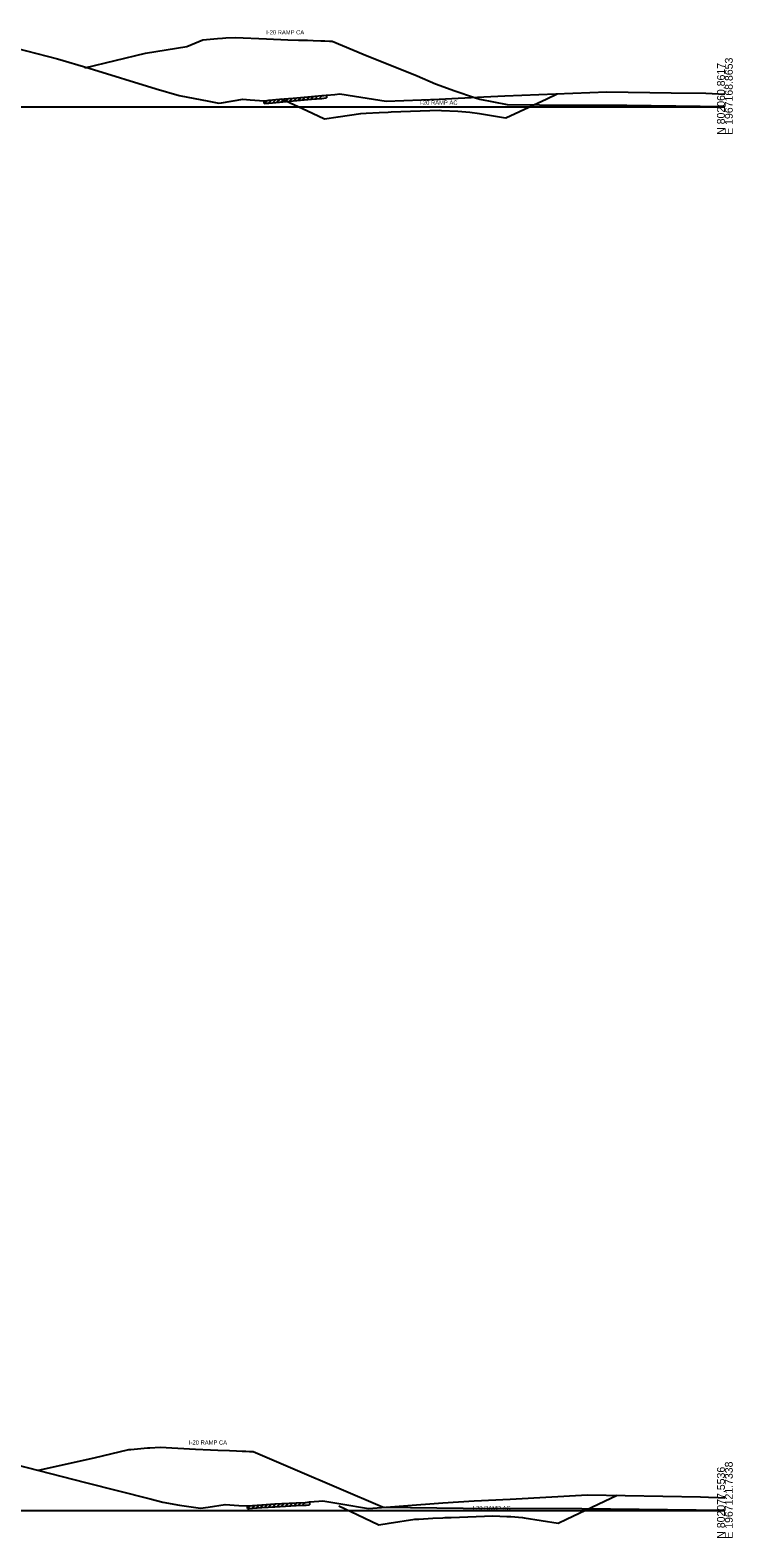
# Model space of a CAD drawing. Extents: x -26 to 1986619, y -10 to 827846.
# Drawn here: x 352 to 603, y 23990 to 24527 of the extents above; entities that cross this region are included whole.
import ezdxf

# ---------------------------------------------------------------- set-up
doc = ezdxf.new("R2010")
doc.units = 0
for name, color, linetype in [('RD_GPK_XS_Cell', 7, 'Continuous'), ('RD_TX_Misc1', 7, 'Continuous'), ('RD_XS_ExGround', 7, 'Continuous'), ('RD_XS_ExPaveRet', 7, 'Continuous'), ('RD_XS_Pave', 7, 'Continuous')]:
    doc.layers.add(name, color=color, linetype=linetype)

msp = doc.modelspace()

# ---------------------------------------------------------------- linework, layer by layer
at = {"layer": 'RD_GPK_XS_Cell'}
for p, q in [((300, 24500), (600, 24500)), ((300, 24000), (600, 24000))]:
    msp.add_line(p, q, dxfattribs=at)
at = {"layer": 'RD_XS_ExGround'}
for points in [[(339.96, 24522.77), (362.21, 24517.09), (373.39, 24513.69), (397.31, 24506.44), (405.57, 24503.96), (416.08, 24501.93), (419.7, 24501.28), (420.65, 24501.43), (428.19, 24502.65), (430.8, 24502.49), (435.86, 24502.14), (436.84, 24502.24), (437.49, 24502.31), (441.22, 24502.67), (446.1, 24503.09), (452.68, 24503.65), (456.35, 24503.95), (457.09, 24504.02), (457.99, 24504.14), (460.96, 24504.4), (462.77, 24504.56), (467.97, 24503.75), (479.27, 24502), (498.23, 24502.73), (514.05, 24503.49), (521.59, 24503.88), (557.93, 24505.29), (580.81, 24504.92), (593.18, 24504.88), (600, 24504.52)], [(343.06, 24017.49), (372.15, 24009.99), (395.23, 24004.26), (399.68, 24002.96), (405.69, 24001.96), (413.09, 24000.82), (415.84, 24001.22), (421.97, 24002.13), (426.76, 24001.88), (429.91, 24001.72), (430.44, 24001.76), (431.64, 24001.82), (434.95, 24002.06), (439.56, 24002.38), (447.22, 24002.77), (450.39, 24002.92), (450.73, 24002.94), (452.02, 24003.1), (455.29, 24003.36), (456.67, 24003.46), (463.18, 24002.37), (472.94, 24000.77), (499.5, 24002.77), (510.62, 24003.49), (523.46, 24004.14), (551.06, 24005.67), (591.36, 24004.9), (594.15, 24004.84), (597.57, 24004.69), (600, 24004.57)]]:
    msp.add_lwpolyline(points, dxfattribs=at)
at = {"layer": 'RD_XS_ExPaveRet'}
for p, q in [((435.86, 24501.14), (436.98, 24502.26)), ((435.86, 24501.14), (435.86, 24502.14)), ((437.36, 24501.3), (438.47, 24502.4)), ((438.86, 24501.44), (439.97, 24502.55)), ((440.36, 24501.58), (441.46, 24502.69)), ((441.86, 24501.72), (442.95, 24502.82)), ((443.36, 24501.85), (444.45, 24502.95)), ((444.86, 24501.98), (445.95, 24503.08)), ((446.1, 24502.09), (452.68, 24502.65)), ((446.36, 24502.11), (447.45, 24503.2)), ((447.86, 24502.24), (448.95, 24503.33)), ((449.36, 24502.37), (450.45, 24503.46)), ((450.86, 24502.49), (451.95, 24503.59)), ((452.36, 24502.62), (453.45, 24503.71)), ((452.68, 24502.65), (456.35, 24502.95)), ((453.86, 24502.74), (454.95, 24503.83)), ((455.36, 24502.87), (456.45, 24503.96)), ((456.35, 24502.95), (457.09, 24503.02)), ((457.09, 24503.02), (457.99, 24503.14)), ((457.99, 24504.14), (457.99, 24503.14)), ((435.86, 24501.14), (436.84, 24501.24)), ((436.84, 24501.24), (437.49, 24501.31)), ((437.49, 24501.31), (441.22, 24501.67)), ((441.22, 24501.67), (446.1, 24502.09)), ((446.41, 24001.73), (447.46, 24002.78)), ((447.91, 24001.8), (448.96, 24002.85)), ((449.41, 24001.87), (450.46, 24002.92)), ((452.02, 24003.1), (452.02, 24002.1)), ((429.91, 24000.72), (430.97, 24001.79)), ((429.91, 24000.72), (429.91, 24001.72)), ((429.91, 24000.72), (430.44, 24000.76)), ((430.44, 24000.76), (431.64, 24000.82)), ((431.41, 24000.81), (432.48, 24001.88)), ((431.64, 24000.82), (434.95, 24001.06)), ((432.91, 24000.91), (433.98, 24001.99)), ((434.41, 24001.02), (435.48, 24002.09)), ((434.95, 24001.06), (439.56, 24001.38)), ((435.91, 24001.12), (436.98, 24002.2)), ((437.41, 24001.23), (438.48, 24002.3)), ((438.91, 24001.33), (439.97, 24002.4)), ((439.56, 24001.38), (447.22, 24001.77)), ((440.41, 24001.42), (441.46, 24002.47)), ((441.91, 24001.5), (442.96, 24002.55)), ((443.41, 24001.57), (444.46, 24002.63)), ((444.91, 24001.65), (445.96, 24002.7)), ((447.22, 24001.77), (450.39, 24001.92)), ((450.39, 24001.92), (450.73, 24001.94)), ((450.73, 24001.94), (452.02, 24002.1))]:
    msp.add_line(p, q, dxfattribs=at)
at = {"layer": 'RD_XS_Pave'}
for points in [[(371.85, 24513.9), (393.56, 24519.1), (408.25, 24521.49), (413.91, 24523.84), (419.23, 24524.3), (420.92, 24524.45), (422.19, 24524.52), (425.59, 24524.71), (436.61, 24524.16), (444.28, 24523.8), (448.03, 24523.76), (451.29, 24523.71), (453.22, 24523.62), (455.96, 24523.49), (456.5, 24523.46), (456.82, 24523.45), (457.39, 24523.42), (459.12, 24523.34), (460.05, 24523.3), (471.13, 24518.77), (490.37, 24510.99), (496.82, 24508.16), (503.78, 24505.71), (510.71, 24503.28), (512.72, 24502.71), (522.36, 24500.85), (545.44, 24500.54), (549.38, 24500.57), (565.1, 24500.56), (600, 24500.13)], [(441.99, 24502.85), (450.97, 24498.64), (457.32, 24495.65), (462.13, 24496.37), (470.27, 24497.57), (472.19, 24497.7), (476.74, 24498.01), (480.03, 24498.11), (481.06, 24498.15), (484.57, 24498.27), (498.32, 24498.74), (498.96, 24498.72), (504.8, 24498.46), (509.11, 24498.12), (512.51, 24497.57), (521.16, 24496.19), (521.97, 24496.06), (536.49, 24502.8), (540.26, 24504.55)], [(355.36, 24014.36), (375.23, 24018.83), (387.54, 24021.76), (388.26, 24021.83), (394.27, 24022.35), (395.01, 24022.39), (398.76, 24022.58), (411.35, 24021.88), (416.72, 24021.6), (419.26, 24021.55), (423.46, 24021.47), (426, 24021.33), (427.95, 24021.23), (428.4, 24021.2), (428.77, 24021.18), (429.32, 24021.15), (430.54, 24021.09), (431.88, 24021.02), (446.81, 24014.6), (477.94, 24001.35), (478.56, 24001.28), (516.14, 24000.77), (522.73, 24000.82), (549.01, 24000.8), (600, 24000.18)], [(462.46, 24001.68), (468.92, 23998.63), (476.69, 23994.96), (480.4, 23995.53), (489.51, 23996.91), (490.9, 23997.01), (495.93, 23997.37), (499.53, 23997.49), (500.2, 23997.52), (502.5, 23997.6), (517.3, 23998.16), (522.24, 23997.96), (523.69, 23997.9), (527.93, 23997.57), (528.46, 23997.49), (540.64, 23995.56), (543.61, 23996.96), (561.65, 24005.45)]]:
    msp.add_lwpolyline(points, dxfattribs=at)

# ---------------------------------------------------------------- texts
at = {"layer": 'RD_GPK_XS_Cell'}
for s, p in [('N 802060.8617', (600, 24490)), ('E 1967168.8653', (602.8, 24490)), ('N 802077.5536', (600, 23990)), ('E 1967121.7338', (602.8, 23990))]:
    msp.add_text(s, height=2.8, rotation=90, dxfattribs=at).set_placement(p)
at = {"layer": 'RD_TX_Misc1'}
for s, p in [('I-20 RAMP CA', (436.5, 24525.76)), ('I-20 RAMP AC', (491.13, 24500.73)), ('I-20 RAMP CA', (409.01, 24023.52)), ('I-20 RAMP AC', (510.06, 24000.15))]:
    msp.add_text(s, height=1.5, dxfattribs=at).set_placement(p)

doc.saveas('drawing.dxf')
